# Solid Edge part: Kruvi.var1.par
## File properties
Author: jaanm
Template: ansi metric part.par
Last saved by: jaanm
Revision: 10
Application: Solid Edge
Accuracy: 0,990
Face Style: Model Default
Coef. of Thermal Exp: 0.0
Thermal Conductivity: 0.0
Specific Heat: 0.0
Modulus of Elasticity: 0.0
Poisson's Ratio: 0.0
Yield Stress: 0.0
Ultimate Stress: 0.0
Elongation: 0.0
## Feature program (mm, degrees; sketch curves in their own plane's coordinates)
sketch for "unnamed Protrusion 1" plane through (0, 0, 0) normal (0, -1, 0) x-axis (1, 0, 0)
  circle centre (0, 0) radius 10
extrude "unnamed Protrusion 1" add finite 12 along +normal
sketch for "ExtrudedProtrusion_2" plane through (0, 0, 0) normal (0, -1, 0) x-axis (1, 0, 0)
  circle centre (0, 0) radius 5
extrude "ExtrudedProtrusion_2" add finite 50 along -normal
chamfer "Chamfer_1" setback 5
helix cutout "HelixCutout_1"  Pitch = 3 mm
sketch for "unnamed Protrusion 2" plane through (0, 0, 0) normal (0, -1, 0) x-axis (1, 0, 0)
  circle centre (0, 0) radius 10
extrude "unnamed Protrusion 2" add to key point along +normal
sketch for "ExtrudedCutout_1" plane through (0, -12, 0) normal (0, -1, 0) x-axis (0, 0, 1)
  line (0, 10) -> (-1.072, 6.9174)
  line (3.287, 9.4443) -> (3.287, 6.1803)
extrude "ExtrudedCutout_1" cut finite 8 along -normal
pattern "unnamed Pattern 1" of "ExtrudedCutout_1"
extrude "unnamed Cutout 1" cut finite 8
extrude "unnamed Cutout 2" cut finite 8
extrude "unnamed Cutout 3" cut finite 8
extrude "unnamed Cutout 4" cut finite 8
extrude "unnamed Cutout 5" cut finite 8
extrude "unnamed Cutout 6" cut finite 8
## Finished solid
Body 1: solid body, 36 faces, 97 edges, 64 vertices.
  Faces by surface: plane 23, cylinder 10, spline 2, cone 1
  Edges by curve: line 56, circle 33, intersection 4, spline 4
Bounding box of the edges (mm; curved faces can reach further): 20.000 x 58.500 x 20.000, from (-10, -12, -10) to (10, 46.5, 10).
Cylindrical faces by radius (mm): R3.5 x1, R5 x1, R7 x7, R10 x1
Conical faces (half-angle, radius in mm at the cone's reference point): 45 deg R5 x1
Planar faces by outward normal: +y 1, -y 8, -z 1, oblique 13
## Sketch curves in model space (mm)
arc centre (0, -12, 0) radius 7 from (-6.9174, -12, -1.072) through (-6.902, -12, 1.1673) to (-6.1803, -12, 3.287)
line (-10, -12, 0) -> (-6.9174, -12, -1.072)
arc centre (0, -12, 0) radius 10 from (-10, -12, 0) through (-9.8601, -12, 1.6668) to (-9.4443, -12, 3.287)
line (-9.4443, -12, 3.287) -> (-6.1803, -12, 3.287)
circle centre (0, 0, 0) radius 5
circle centre (0, 0, 0) radius 10
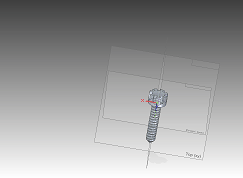
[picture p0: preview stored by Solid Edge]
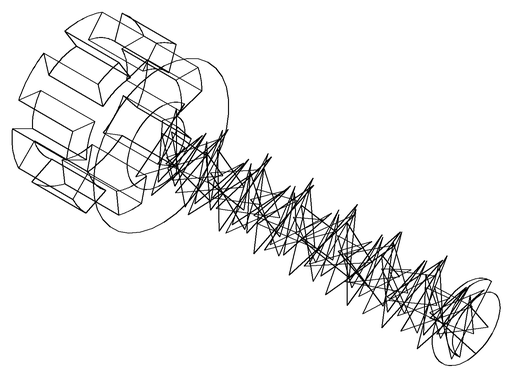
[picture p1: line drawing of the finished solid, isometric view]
